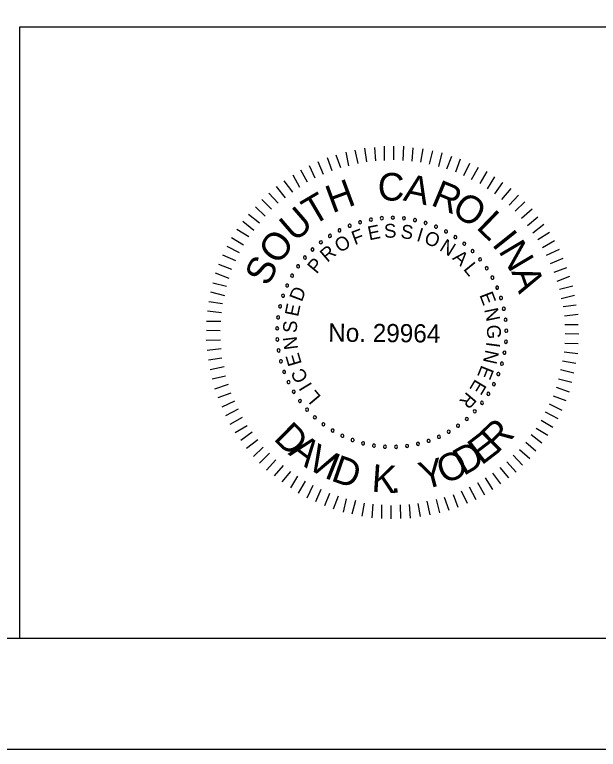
# Model space of a CAD drawing. Extents: x -133.1 to -97, y -110.1 to -88.1.
# Drawn here: x -110.531 to -107.904, y -110.103 to -106.798 of the extents above; entities that cross this region are included whole.
import ezdxf

# ---------------------------------------------------------------- set-up
doc = ezdxf.new("R2010")
doc.units = 0
for name, color, linetype in [('BR_BORDER LINES', 7, 'Continuous'), ('BR_TEXT', 7, 'Continuous'), ('Level 31', 7, 'Continuous')]:
    doc.layers.add(name, color=color, linetype=linetype)

msp = doc.modelspace()

# ---------------------------------------------------------------- linework, layer by layer
at = {"layer": 'BR_BORDER LINES'}
for p, q in [((-110.5071, -106.8526), (-105.1419, -106.8526)), ((-110.5071, -109.6027), (-110.5071, -106.8526)), ((-131.3076, -109.6027), (-97.6416, -109.6027))]:
    msp.add_line(p, q, dxfattribs=at)
at = {"layer": 'BR_TEXT'}
for p, q in [((-108.9849, -107.467), (-108.999, -107.4076)), ((-108.9454, -107.4595), (-108.9543, -107.3986)), ((-108.9059, -107.4556), (-108.9097, -107.3946)), ((-108.8664, -107.4533), (-108.8658, -107.389)), ((-108.8243, -107.4511), (-108.8238, -107.3893)), ((-108.7823, -107.454), (-108.78, -107.3897)), ((-108.742, -107.4569), (-108.7372, -107.396)), ((-108.7034, -107.4615), (-108.6926, -107.4007)), ((-108.6631, -107.4696), (-108.6489, -107.4105)), ((-109.1019, -107.4995), (-109.1229, -107.4409)), ((-109.0623, -107.4869), (-109.0842, -107.4292)), ((-109.0262, -107.4769), (-109.0394, -107.4159)), ((-108.622, -107.4802), (-108.606, -107.4195)), ((-108.5852, -107.4908), (-108.5633, -107.4335)), ((-108.5458, -107.504), (-108.5239, -107.4459)), ((-109.1777, -107.5332), (-109.2039, -107.4771)), ((-109.1406, -107.5163), (-109.1642, -107.4603)), ((-108.5099, -107.5215), (-108.482, -107.4659)), ((-109.2122, -107.5509), (-109.2426, -107.4966)), ((-108.474, -107.539), (-108.4427, -107.4834)), ((-108.4364, -107.5573), (-108.4042, -107.5035)), ((-109.2786, -107.5958), (-109.3177, -107.5449)), ((-109.2475, -107.5746), (-109.278, -107.5203)), ((-108.4031, -107.5816), (-108.3692, -107.5278)), ((-109.3123, -107.6213), (-109.3522, -107.5712)), ((-108.3699, -107.6033), (-108.3334, -107.553)), ((-109.3451, -107.6459), (-109.3868, -107.6009)), ((-108.3375, -107.6293), (-108.2968, -107.5799)), ((-108.3059, -107.6545), (-108.2627, -107.6102)), ((-109.3745, -107.6731), (-109.4188, -107.629)), ((-108.2779, -107.6822), (-108.2346, -107.6388)), ((-109.4039, -107.7038), (-109.4474, -107.6614)), ((-108.2498, -107.7133), (-108.2022, -107.6716)), ((-109.4291, -107.7353), (-109.4786, -107.6963)), ((-108.2226, -107.7453), (-108.1759, -107.707)), ((-109.4551, -107.7686), (-109.5046, -107.7287)), ((-108.1988, -107.779), (-108.1496, -107.7399)), ((-109.4768, -107.7976), (-109.5306, -107.7645)), ((-108.1768, -107.8083), (-108.1242, -107.7761)), ((-109.5012, -107.8343), (-109.5549, -107.8021)), ((-109.5186, -107.8685), (-109.575, -107.8405)), ((-108.1548, -107.8454), (-108.1013, -107.8141)), ((-108.137, -107.8799), (-108.0793, -107.8529)), ((-109.5361, -107.9052), (-109.5933, -107.8798)), ((-108.1193, -107.9169), (-108.0624, -107.8925)), ((-109.5536, -107.9437), (-109.6117, -107.9218)), ((-108.1025, -107.9557), (-108.0456, -107.9347)), ((-109.5659, -107.9839), (-109.6275, -107.9611)), ((-108.0891, -107.9961), (-108.0314, -107.9743)), ((-109.5782, -108.0199), (-109.639, -108.0048)), ((-108.079, -108.0322), (-108.0189, -108.0181)), ((-109.5854, -108.0619), (-109.6479, -108.0459)), ((-108.0708, -108.0744), (-108.0106, -108.0594)), ((-109.596, -108.0978), (-109.6569, -108.0896)), ((-108.0625, -108.1105), (-108.0033, -108.1032)), ((-109.6006, -108.139), (-109.6624, -108.1316)), ((-108.056, -108.1517), (-107.995, -108.1454)), ((-109.6035, -108.1784), (-109.6679, -108.1779)), ((-108.0546, -108.1912), (-107.9945, -108.1917)), ((-109.6056, -108.2196), (-109.6682, -108.219)), ((-108.0524, -108.2324), (-107.9915, -108.2329)), ((-109.6042, -108.2625), (-109.6686, -108.2637)), ((-109.602, -108.3012), (-109.6638, -108.3083)), ((-108.0553, -108.2753), (-107.9952, -108.2775)), ((-108.0574, -108.3139), (-107.9965, -108.3221)), ((-109.598, -108.3424), (-109.659, -108.3513)), ((-108.0645, -108.355), (-108.0054, -108.365)), ((-109.5881, -108.3819), (-109.6508, -108.3951)), ((-108.0735, -108.3944), (-108.0135, -108.4087)), ((-109.5815, -108.4241), (-109.6426, -108.4381)), ((-108.0824, -108.4364), (-108.0224, -108.4515)), ((-109.5698, -108.461), (-109.6318, -108.482)), ((-109.5582, -108.4997), (-109.6167, -108.5207)), ((-108.093, -108.4732), (-108.0357, -108.4951)), ((-109.5413, -108.5368), (-109.599, -108.5638)), ((-108.107, -108.5117), (-108.0506, -108.5337)), ((-108.1245, -108.5485), (-108.0681, -108.5764)), ((-109.5244, -108.573), (-109.5813, -108.6025)), ((-108.1428, -108.5844), (-108.0856, -108.6149)), ((-109.5076, -108.61), (-109.5619, -108.6413)), ((-108.1612, -108.6211), (-108.1082, -108.6533)), ((-109.4838, -108.6471), (-109.5382, -108.6784)), ((-108.1838, -108.6579), (-108.1317, -108.69)), ((-109.4626, -108.6765), (-109.5127, -108.713)), ((-108.2063, -108.6868), (-108.1577, -108.7242)), ((-109.4372, -108.7101), (-109.4873, -108.7492)), ((-108.2306, -108.7201), (-108.1846, -108.76)), ((-109.4125, -108.7438), (-109.4567, -108.7847)), ((-108.2583, -108.7533), (-108.2115, -108.7949)), ((-109.3836, -108.7698), (-109.4286, -108.8149)), ((-109.3547, -108.8001), (-109.3971, -108.8461)), ((-108.2869, -108.7789), (-108.2444, -108.8247)), ((-109.3222, -108.8261), (-109.363, -108.873)), ((-108.3474, -108.8341), (-108.3075, -108.8817)), ((-108.3155, -108.8087), (-108.273, -108.8553)), ((-109.289, -108.8521), (-109.3289, -108.8998)), ((-108.3802, -108.8596), (-108.3446, -108.908)), ((-109.2583, -108.8738), (-109.2896, -108.9259)), ((-109.2233, -108.8964), (-109.2546, -108.9502)), ((-108.4139, -108.8808), (-108.3808, -108.9334)), ((-109.1891, -108.9164), (-109.2162, -108.972)), ((-109.1523, -108.9339), (-109.1769, -108.9895)), ((-108.4855, -108.9222), (-108.455, -108.9783)), ((-108.4475, -108.9028), (-108.4162, -108.9571)), ((-109.1139, -108.9514), (-109.1358, -109.0079)), ((-109.0745, -108.9637), (-109.0973, -109.0219)), ((-108.5578, -108.956), (-108.5368, -109.0128)), ((-108.5216, -108.9391), (-108.4947, -108.9951)), ((-109.0386, -108.9761), (-109.0528, -109.0351)), ((-108.9974, -108.9832), (-109.0126, -109.0449)), ((-108.9581, -108.9947), (-108.968, -109.053)), ((-108.9186, -108.9993), (-108.9234, -109.0611)), ((-108.7161, -108.9967), (-108.7062, -109.0552)), ((-108.6756, -108.9859), (-108.6624, -109.0478)), ((-108.6344, -108.9794), (-108.6194, -109.0387)), ((-108.5974, -108.9676), (-108.5764, -109.0262)), ((-108.8792, -109.0022), (-108.8797, -109.064)), ((-108.8372, -109.0052), (-108.8377, -109.0661)), ((-108.7951, -109.0029), (-108.7939, -109.0648)), ((-108.7547, -109.0007), (-108.7509, -109.0625))]:
    msp.add_line(p, q, dxfattribs=at)
for centre, start, end in [((-108.8784, -107.7129), 5.0653, 185.0653), ((-108.8286, -107.711), 359.5268, 179.5268), ((-108.8286, -107.711), 179.5268, 359.5268), ((-108.7789, -107.714), 353.9884, 173.9884), ((-109.0235, -107.7471), 21.6807, 201.6807), ((-108.9763, -107.7311), 16.1422, 196.1422), ((-108.9763, -107.7311), 196.1422, 16.1422), ((-108.9278, -107.7196), 10.6038, 190.6038), ((-108.9278, -107.7196), 190.6038, 10.6038), ((-108.8784, -107.7129), 185.0653, 5.0653), ((-108.7789, -107.714), 173.9884, 353.9884), ((-108.7296, -107.7217), 168.4499, 348.4499), ((-108.7296, -107.7217), 348.4499, 168.4499), ((-108.6814, -107.7341), 162.9114, 342.9114), ((-108.6814, -107.7341), 342.9114, 162.9114), ((-108.6345, -107.7511), 337.373, 157.373), ((-109.0689, -107.7676), 27.2191, 207.2191), ((-109.0689, -107.7676), 207.2191, 27.2191), ((-109.0235, -107.7471), 201.6807, 21.6807), ((-108.6345, -107.7511), 157.373, 337.373), ((-108.5896, -107.7726), 151.8345, 331.8345), ((-108.5896, -107.7726), 331.8345, 151.8345), ((-109.1121, -107.7925), 32.7576, 212.7576), ((-109.1121, -107.7925), 212.7576, 32.7576), ((-108.5469, -107.7983), 146.2961, 326.2961), ((-108.5469, -107.7983), 326.2961, 146.2961), ((-109.1527, -107.8213), 38.2961, 218.2961), ((-109.1527, -107.8213), 218.2961, 38.2961), ((-108.5069, -107.828), 140.7576, 320.7576), ((-108.5069, -107.828), 320.7576, 140.7576), ((-109.1903, -107.854), 43.8345, 223.8345), ((-109.1903, -107.854), 223.8345, 43.8345), ((-108.4699, -107.8614), 135.2191, 315.2191), ((-108.4699, -107.8614), 315.2191, 135.2191), ((-109.2246, -107.8901), 49.373, 229.373), ((-109.2246, -107.8901), 229.373, 49.373), ((-108.4363, -107.8982), 129.6807, 309.6807), ((-108.4363, -107.8982), 309.6807, 129.6807), ((-109.2553, -107.9294), 54.9114, 234.9114), ((-109.2553, -107.9294), 234.9114, 54.9114), ((-108.4065, -107.9381), 124.1422, 304.1422), ((-108.4065, -107.9381), 304.1422, 124.1422), ((-109.282, -107.9715), 60.4499, 240.4499), ((-109.282, -107.9715), 240.4499, 60.4499), ((-108.3806, -107.9807), 118.6038, 298.6038), ((-108.3806, -107.9807), 298.6038, 118.6038), ((-109.3045, -108.0159), 65.9884, 245.9884), ((-109.3045, -108.0159), 245.9884, 65.9884), ((-108.359, -108.0256), 113.0653, 293.0653), ((-108.359, -108.0256), 293.0653, 113.0653), ((-109.3227, -108.0623), 71.5268, 251.5268), ((-109.3227, -108.0623), 251.5268, 71.5268), ((-108.3418, -108.0724), 107.5268, 287.5268), ((-108.3418, -108.0724), 287.5268, 107.5268), ((-109.3363, -108.1103), 77.0653, 257.0653), ((-109.3363, -108.1103), 257.0653, 77.0653), ((-108.3292, -108.1206), 101.9884, 281.9884), ((-108.3292, -108.1206), 281.9884, 101.9884), ((-109.3452, -108.1593), 82.6038, 262.6038), ((-109.3452, -108.1593), 262.6038, 82.6038), ((-108.3213, -108.1698), 96.4499, 276.4499), ((-108.3213, -108.1698), 276.4499, 96.4499), ((-109.3493, -108.209), 88.1422, 268.1422), ((-109.3493, -108.209), 268.1422, 88.1422), ((-108.3182, -108.2195), 90.9114, 270.9114), ((-108.3182, -108.2195), 270.9114, 90.9114), ((-109.3486, -108.2588), 93.6807, 273.6807), ((-109.3486, -108.2588), 273.6807, 93.6807), ((-108.3199, -108.2693), 85.373, 265.373), ((-108.3199, -108.2693), 265.373, 85.373), ((-109.3431, -108.3083), 99.2191, 279.2191), ((-109.3431, -108.3083), 279.2191, 99.2191), ((-108.3265, -108.3187), 79.8345, 259.8345), ((-108.3265, -108.3187), 259.8345, 79.8345), ((-109.3328, -108.3571), 104.7576, 284.7576), ((-109.3328, -108.3571), 284.7576, 104.7576), ((-108.3377, -108.3673), 74.2961, 254.2961), ((-108.3377, -108.3673), 254.2961, 74.2961), ((-109.3179, -108.4046), 110.2961, 290.2961), ((-109.3179, -108.4046), 290.2961, 110.2961), ((-108.3536, -108.4145), 68.7576, 248.7576), ((-108.3536, -108.4145), 248.7576, 68.7576), ((-109.2985, -108.4505), 115.8345, 295.8345), ((-109.2985, -108.4505), 295.8345, 115.8345), ((-108.374, -108.46), 63.2191, 243.2191), ((-108.374, -108.46), 243.2191, 63.2191), ((-109.2747, -108.4943), 121.373, 301.373), ((-109.2747, -108.4943), 301.373, 121.373), ((-108.3986, -108.5033), 57.6807, 237.6807), ((-108.3986, -108.5033), 237.6807, 57.6807), ((-109.2468, -108.5356), 126.9114, 306.9114), ((-109.2468, -108.5356), 306.9114, 126.9114), ((-108.4273, -108.544), 52.1422, 232.1422), ((-109.2151, -108.574), 132.4499, 312.4499), ((-109.2151, -108.574), 312.4499, 132.4499), ((-108.4273, -108.544), 232.1422, 52.1422), ((-109.1798, -108.6092), 317.9884, 137.9884), ((-108.4599, -108.5818), 46.6038, 226.6038), ((-108.4599, -108.5818), 226.6038, 46.6038), ((-109.1798, -108.6092), 137.9884, 317.9884), ((-109.1413, -108.6408), 143.5268, 323.5268), ((-109.1413, -108.6408), 323.5268, 143.5268), ((-108.4959, -108.6162), 41.0653, 221.0653), ((-108.4959, -108.6162), 221.0653, 41.0653), ((-109.0999, -108.6685), 149.0653, 329.0653), ((-109.0999, -108.6685), 329.0653, 149.0653), ((-108.577, -108.6739), 29.9884, 209.9884), ((-108.5351, -108.647), 35.5268, 215.5268), ((-108.5351, -108.647), 215.5268, 35.5268), ((-109.056, -108.6921), 154.6038, 334.6038), ((-109.056, -108.6921), 334.6038, 154.6038), ((-108.6214, -108.6966), 24.4499, 204.4499), ((-108.6214, -108.6966), 204.4499, 24.4499), ((-108.577, -108.6739), 209.9884, 29.9884), ((-109.01, -108.7114), 160.1422, 340.1422), ((-109.01, -108.7114), 340.1422, 160.1422), ((-108.9624, -108.7261), 165.6807, 345.6807), ((-108.9624, -108.7261), 345.6807, 165.6807), ((-108.9136, -108.7362), 171.2191, 351.2191), ((-108.9136, -108.7362), 351.2191, 171.2191), ((-108.8641, -108.7415), 356.7576, 176.7576), ((-108.8142, -108.742), 2.2961, 182.2961), ((-108.7646, -108.7377), 7.8345, 187.8345), ((-108.7156, -108.7287), 13.373, 193.373), ((-108.7156, -108.7287), 193.373, 13.373), ((-108.6677, -108.7149), 18.9114, 198.9114), ((-108.6677, -108.7149), 198.9114, 18.9114), ((-108.8641, -108.7415), 176.7576, 356.7576), ((-108.8142, -108.742), 182.2961, 2.2961), ((-108.7646, -108.7377), 187.8345, 7.8345)]:
    msp.add_arc(centre, 0.00701, start, end, dxfattribs=at)
at = {"layer": 'Level 31'}
msp.add_lwpolyline([(-133.1409, -110.1026), (-97.141, -110.1026), (-97.141, -88.1026), (-133.1409, -88.1026)], close=True, dxfattribs=at)

# ---------------------------------------------------------------- texts
at = {"layer": 'BR_TEXT'}
for s, height, rotation, p in [('C', 0.1241, 359.5482, (-108.8971, -107.6334)), ('H', 0.1241, 20.3637, (-109.1015, -107.6918)), ('A', 0.1241, 348.1981, (-108.7857, -107.6327)), ('R', 0.1241, 337.4344, (-108.6624, -107.6525)), ('T', 0.1241, 30.4992, (-109.1894, -107.7493)), ('O', 0.1239, 326.5869, (-108.5702, -107.6893)), ('U', 0.1241, 40.8022, (-109.2706, -107.824)), ('L', 0.1241, 315.9488, (-108.4576, -107.7571)), ('E', 0.0622, 11.4103, (-108.9351, -107.813)), ('S', 0.0622, 2.208, (-108.8672, -107.802)), ('S', 0.0622, 352.6608, (-108.796, -107.8022)), ('O', 0.1241, 52.0267, (-109.3451, -107.928)), ('F', 0.0622, 20.6127, (-109.0002, -107.8346)), ('I', 0.0622, 343.1136, (-108.7257, -107.8142)), ('O', 0.0622, 338.4392, (-108.6923, -107.8243)), ('I', 0.1241, 308.6613, (-108.3862, -107.8313)), ('O', 0.0622, 30.8477, (-109.0676, -107.8707)), ('N', 0.0622, 328.2042, (-108.6227, -107.8557)), ('N', 0.1241, 300.7037, (-108.3556, -107.8607)), ('R', 0.0622, 40.3949, (-109.1237, -107.9145)), ('A', 0.0622, 318.657, (-108.5637, -107.8958)), ('S', 0.1239, 63.2511, (-109.3905, -108.0236)), ('P', 0.0622, 49.9421, (-109.1718, -107.9671)), ('L', 0.0622, 309.4546, (-108.5139, -107.9431)), ('A', 0.1241, 289.4792, (-108.2964, -107.9538)), ('D', 0.0622, 69.0364, (-109.2388, -108.0924)), ('E', 0.0622, 291.049, (-108.44, -108.0584)), ('E', 0.0622, 78.2388, (-109.2553, -108.1591)), ('N', 0.0622, 281.8466, (-108.4179, -108.1234)), ('S', 0.0622, 87.786, (-109.2611, -108.2301)), ('No. 29964', 0.08175, 359.5268, (-109.1199, -108.2685)), ('G', 0.0622, 272.2995, (-108.4061, -108.1937)), ('N', 0.0622, 97.3332, (-109.2549, -108.3011)), ('I', 0.0622, 262.4084, (-108.4065, -108.2675)), ('E', 0.0622, 106.5355, (-109.2379, -108.3677)), ('N', 0.0622, 257.7339, (-108.411, -108.3022)), ('C', 0.0622, 116.4266, (-109.208, -108.4352)), ('E', 0.0622, 248.1867, (-108.4291, -108.3711)), ('I', 0.0622, 121.1011, (-109.1899, -108.4651)), ('E', 0.0622, 238.9844, (-108.457, -108.4339)), ('L', 0.0622, 129.9595, (-109.1493, -108.5172)), ('R', 0.0622, 229.782, (-108.4947, -108.4913)), ('D', 0.1236, 315.4053, (-109.3698, -108.7078)), ('R', 0.1236, 44.5947, (-108.3589, -108.7734)), ('E', 0.1236, 37.5339, (-108.4295, -108.8273)), ('A', 0.1236, 322.8377, (-109.3032, -108.7735)), ('V', 0.1236, 330.5179, (-109.226, -108.8317)), ('D', 0.1236, 30.1015, (-108.5104, -108.8742)), ('O', 0.1236, 22.4212, (-108.5997, -108.9113)), ('I', 0.1236, 338.1981, (-109.1418, -108.8791)), ('D', 0.1236, 340.7995, (-109.1119, -108.8925)), ('Y', 0.1236, 14.8649, (-108.6915, -108.9358)), ('K', 0.1236, 356.098, (-108.9267, -108.943)), ('.', 0.1236, 3.1588, (-108.838, -108.9494))]:
    msp.add_text(s, height=height, rotation=rotation, dxfattribs=at).set_placement(p)

doc.saveas('drawing.dxf')
